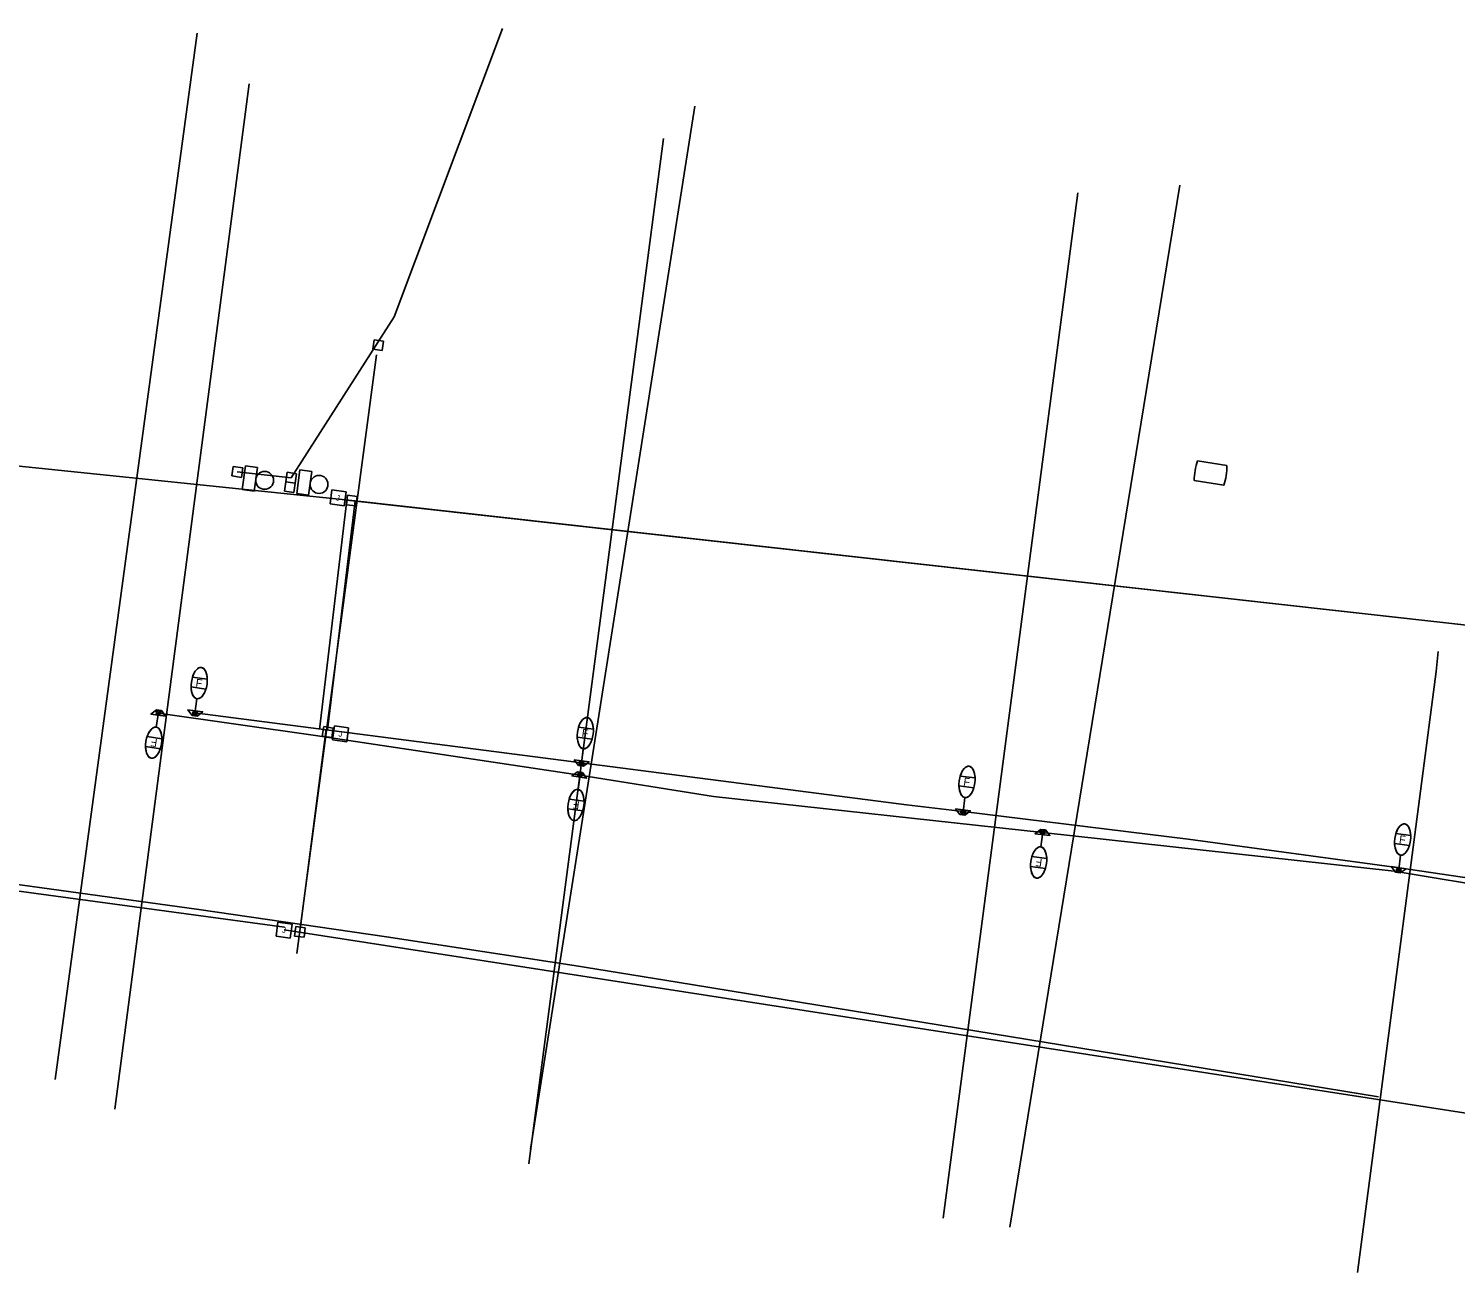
# Model space of a CAD drawing. Extents: x 915723 to 927758, y 636394 to 638609.
# Drawn here: x 924821 to 925539, y 636655 to 637280 of the extents above; entities that cross this region are included whole.
import ezdxf

# ---------------------------------------------------------------- set-up
doc = ezdxf.new("R2010")
doc.units = 0
for name, color, linetype in [('ConduitBM', 7, 'Continuous'), ('ConduitJB', 7, 'Continuous'), ('ConduitOT', 7, 'Continuous'), ('DrShaftConc', 7, 'Continuous'), ('LoadCenter', 7, 'Continuous'), ('Masonry_h', 7, 'Continuous'), ('Miscellaneous2', 7, 'Continuous'), ('PoleLight', 7, 'Continuous'), ('PullBox', 7, 'Continuous'), ('SchemHydraulicAux', 7, 'Continuous'), ('TextStructuresLabel', 7, 'Continuous')]:
    doc.layers.add(name, color=color, linetype=linetype)

msp = doc.modelspace()

# ---------------------------------------------------------------- linework, layer by layer
at = {"layer": 'ConduitBM'}
for p, q in [((924904.95, 636936.09), (925099.22, 636910.93)), ((924787.88, 636850.28), (924949.92, 636828.26)), ((925915.45, 636677.29), (924949.76, 636826.97))]:
    msp.add_line(p, q, dxfattribs=at)
for points in [[(924886.59, 636935.94), (924965.57, 636924.72), (925098.46, 636904.69)], [(925099.24, 636910.93), (925262.58, 636889.84), (925291.07, 636886.41)], [(925098.47, 636904.68), (925165.57, 636894.03), (925331.01, 636875.86)], [(925291.06, 636886.41), (925404.18, 636872.54), (925510.18, 636858.09)], [(925331.01, 636875.86), (925426.89, 636865.33), (925507.73, 636856.45), (925564.25, 636847.04)], [(925510.23, 636858.22), (925615.9, 636842.6), (925678.54, 636835.95), (925719.06, 636830.44)]]:
    msp.add_lwpolyline(points, dxfattribs=at)
at = {"layer": 'ConduitJB'}
for p, q in [((924783.08, 637063.49), (924983.84, 637042.69)), ((924983.84, 637042.69), (925933.76, 636936.47))]:
    msp.add_line(p, q, dxfattribs=at)
at = {"layer": 'ConduitOT'}
for p, q in [((924985.42, 637042.51), (924971.54, 636927.46)), ((924970.88, 636927.76), (924957.98, 636828.59))]:
    msp.add_line(p, q, dxfattribs=at)
at = {"layer": 'DrShaftConc'}
for p, q in [((924906.12, 637277.59), (924834.67, 636751.85)), ((925156.25, 637240.87), (925073.57, 636716.78)), ((925399.97, 637201.27), (925314.54, 636677.62)), ((924956.18, 636815.06), (924996.16, 637115.96)), ((924967.59, 636927.62), (924981.35, 637042.94)), ((925933.76, 636936.47), (924981.35, 637042.94))]:
    msp.add_line(p, q, dxfattribs=at)
msp.add_lwpolyline([(924148.09, 636918.61), (924243.21, 636911.23), (924338.26, 636903.05), (924433.24, 636894.08), (924528.14, 636884.3), (924622.95, 636873.74), (924717.68, 636862.37), (924812.3, 636850.22), (924906.82, 636837.27), (925001.23, 636823.53), (925095.52, 636808.99), (925147.31, 636800.67), (925147.31, 636800.67), (925499.92, 636743.14)], dxfattribs=at)
at = {"layer": 'LoadCenter'}
for p, q in [((924928.74, 637048.33), (924930.37, 637060.22)), ((924930.37, 637060.22), (924936.31, 637059.4)), ((924936.31, 637059.4), (924934.69, 637047.51)), ((924956.07, 637046.29), (924957.7, 637058.18)), ((924957.7, 637058.18), (924963.64, 637057.37)), ((924963.64, 637057.37), (924962.02, 637045.48)), ((924934.69, 637047.51), (924928.74, 637048.33)), ((924962.02, 637045.48), (924956.07, 637046.29))]:
    msp.add_line(p, q, dxfattribs=at)
for centre in [(924939.96, 637052.85), (924967.29, 637050.82)]:
    msp.add_circle(centre, 4.5, dxfattribs=at)
at = {"layer": 'Masonry_h'}
for p, q in [((924932.21, 637252.04), (924864.58, 636736.82)), ((925140.42, 637224.71), (925072.79, 636709.49)), ((925348.64, 637197.38), (925281.01, 636682.16)), ((925529.86, 636966.83), (925528.87, 636956.88)), ((925528.87, 636956.88), (925489.22, 636654.83))]:
    msp.add_line(p, q, dxfattribs=at)
at = {"layer": 'Miscellaneous2'}
for p, q in [((925423.67, 637060.25), (925408.84, 637062.67)), ((925408.84, 637062.67), (925408.84, 637062.67)), ((925407.23, 637052.8), (925407.23, 637052.8)), ((925407.23, 637052.8), (925422.06, 637050.38))]:
    msp.add_line(p, q, dxfattribs=at)
for start_param, end_param in [(1.249648, 1.891946), (4.391271, 5.033538), (4.391241, 4.391271)]:
    msp.add_ellipse((925415.45, 637056.52), major_axis=(2.55, 15.63), ratio=0.5, start_param=start_param, end_param=end_param, dxfattribs=at)
at = {"layer": 'PoleLight'}
for p, q in [((924903.71, 636953.98), (924911.15, 636952.91)), ((924910.44, 636947.96), (924903, 636949.03)), ((924904.9, 636935.78), (924905.95, 636943.13)), ((924886.65, 636936.21), (924885.48, 636928.88)), ((925097.74, 636928.78), (925105.19, 636927.82)), ((924880.92, 636924.12), (924888.34, 636922.93)), ((925104.55, 636922.86), (925097.1, 636923.82)), ((924887.55, 636917.99), (924880.13, 636919.18)), ((925099.18, 636910.6), (925100.13, 636917.96)), ((925098.48, 636904.96), (925097.5, 636897.6)), ((925296.41, 636898.36), (925288.96, 636899.34)), ((925289.61, 636904.29), (925297.06, 636903.32)), ((925093.05, 636892.73), (925100.5, 636891.73)), ((925291.02, 636886.11), (925291.98, 636893.47)), ((925099.83, 636886.77), (925092.39, 636887.77)), ((925331.06, 636876.04), (925330.07, 636868.68)), ((925508.58, 636875.33), (925516.03, 636874.35)), ((925325.63, 636863.81), (925333.07, 636862.81)), ((925515.38, 636869.39), (925507.93, 636870.37)), ((925509.98, 636857.15), (925510.95, 636864.51)), ((925332.41, 636857.86), (925324.96, 636858.86))]:
    msp.add_line(p, q, dxfattribs=at)
for points in [[(924888.05, 636937.26), (924885.57, 636937.59), (924882.76, 636935.45), (924890.19, 636934.44)], [(924888.05, 636937.26), (924885.57, 636937.59), (924882.76, 636935.45), (924890.19, 636934.44)], [(924906.03, 636934.44), (924903.56, 636934.76), (924901.4, 636937.56), (924908.83, 636936.59)], [(924906.03, 636934.44), (924903.56, 636934.76), (924901.4, 636937.56), (924908.83, 636936.59)], [(925100.23, 636909.28), (925097.75, 636909.61), (925095.59, 636912.41), (925103.03, 636911.44)], [(925100.23, 636909.28), (925097.75, 636909.61), (925095.59, 636912.41), (925103.03, 636911.44)], [(925099.72, 636906.01), (925097.25, 636906.39), (925094.4, 636904.3), (925101.81, 636903.16)], [(925099.72, 636906.01), (925097.25, 636906.39), (925094.4, 636904.3), (925101.81, 636903.16)], [(925291.93, 636884.64), (925289.45, 636884.95), (925287.28, 636887.74), (925294.72, 636886.81)], [(925291.93, 636884.64), (925289.45, 636884.95), (925287.28, 636887.74), (925294.72, 636886.81)], [(925332.47, 636877.21), (925329.98, 636877.47), (925327.23, 636875.27), (925334.68, 636874.45)], [(925332.47, 636877.21), (925329.98, 636877.47), (925327.23, 636875.27), (925334.68, 636874.45)], [(925510.81, 636855.63), (925508.35, 636856.02), (925506.26, 636858.87), (925513.67, 636857.72)], [(925510.81, 636855.63), (925508.35, 636856.02), (925506.26, 636858.87), (925513.67, 636857.72)]]:
    msp.add_lwpolyline(points, close=True, dxfattribs=at)
for centre, radius in [((924886.65, 636936.19), 1.14), ((924886.65, 636936.21), 0.569), ((924904.94, 636935.84), 1.14), ((924904.9, 636935.78), 0.569), ((925099.21, 636910.72), 1.14), ((925099.18, 636910.6), 0.569), ((925098.48, 636904.89), 1.14), ((925098.48, 636904.96), 0.569), ((925291.02, 636886.11), 1.14), ((925291.02, 636886.11), 0.569), ((925331.06, 636876.04), 1.14), ((925331.06, 636876.04), 0.569), ((925509.98, 636857.15), 1.14), ((925509.98, 636857.15), 0.569)]:
    msp.add_circle(centre, radius, dxfattribs=at)
for centre, major_axis in [((924907.07, 636950.97), (-1.12, -7.84)), ((924884.23, 636921.06), (1.25, 7.82)), ((925101.14, 636925.82), (-1.01, -7.85)), ((925293.01, 636901.33), (-1.03, -7.85)), ((925096.44, 636889.75), (1.05, 7.85)), ((925511.98, 636872.36), (-1.03, -7.85)), ((925329.02, 636860.84), (1.05, 7.85))]:
    msp.add_ellipse(centre, major_axis=major_axis, ratio=0.5, dxfattribs=at)
for centre, major_axis, start_param, end_param in [((924907.07, 636950.97), (-1.12, -7.84), 1.891945, 4.391241), ((924907.07, 636950.97), (-1.12, -7.84), 5.033538, 6.283185), ((924907.07, 636950.97), (-1.12, -7.84), 0, 0.847605), ((924907.07, 636950.97), (-1.12, -7.84), 0.847605, 1.249648), ((924884.23, 636921.06), (1.25, 7.82), 0, 0.847605), ((924884.23, 636921.06), (1.25, 7.82), 5.033538, 6.283185), ((925101.14, 636925.82), (-1.01, -7.85), 1.891945, 4.391241), ((924884.23, 636921.06), (1.25, 7.82), 0.847605, 1.249648), ((925101.14, 636925.82), (-1.01, -7.85), 5.033538, 6.283185), ((925101.14, 636925.82), (-1.01, -7.85), 0.847605, 1.249648), ((924884.23, 636921.06), (1.25, 7.82), 1.891945, 4.391241), ((925101.14, 636925.82), (-1.01, -7.85), 0, 0.847605), ((925293.01, 636901.33), (-1.03, -7.85), 1.891945, 4.391241), ((925293.01, 636901.33), (-1.03, -7.85), 5.033538, 6.283185), ((925096.44, 636889.75), (1.05, 7.85), 0.847605, 1.249648), ((925096.44, 636889.75), (1.05, 7.85), 0, 0.847605), ((925096.44, 636889.75), (1.05, 7.85), 5.033538, 6.283185), ((925293.01, 636901.33), (-1.03, -7.85), 0, 0.847605), ((925293.01, 636901.33), (-1.03, -7.85), 0.847605, 1.249648), ((925096.44, 636889.75), (1.05, 7.85), 1.891945, 4.391241), ((925511.98, 636872.36), (-1.03, -7.85), 1.891945, 4.391241), ((925329.02, 636860.84), (1.05, 7.85), 0.847605, 1.249648), ((925329.02, 636860.84), (1.05, 7.85), 0, 0.847605), ((925329.02, 636860.84), (1.05, 7.85), 5.033538, 6.283185), ((925511.98, 636872.36), (-1.03, -7.85), 5.033538, 6.283185), ((925511.98, 636872.36), (-1.03, -7.85), 0, 0.847605), ((925511.98, 636872.36), (-1.03, -7.85), 0.847605, 1.249648), ((925329.02, 636860.84), (1.05, 7.85), 1.891945, 4.391241)]:
    msp.add_ellipse(centre, major_axis=major_axis, ratio=0.5, start_param=start_param, end_param=end_param, dxfattribs=at)
at = {"layer": 'PullBox'}
for p, q in [((924994.27, 637118.75), (924994.98, 637123.51)), ((924994.98, 637123.51), (924999.73, 637122.79)), ((924999.73, 637122.79), (924999.02, 637118.04)), ((924999.02, 637118.04), (924994.27, 637118.75)), ((924923.5, 637055.05), (924924.21, 637059.8)), ((924924.21, 637059.8), (924928.96, 637059.09)), ((924928.96, 637059.09), (924928.25, 637054.33)), ((924928.25, 637054.33), (924923.5, 637055.05)), ((924949.87, 637047.41), (924950.58, 637052.16)), ((924950.58, 637052.16), (924951.29, 637056.91)), ((924955.33, 637051.45), (924950.58, 637052.16)), ((924950.58, 637052.16), (924955.33, 637051.45)), ((924951.29, 637056.91), (924956.04, 637056.2)), ((924955.33, 637051.45), (924954.62, 637046.7)), ((924956.04, 637056.2), (924955.33, 637051.45)), ((924954.62, 637046.7), (924949.87, 637047.41)), ((924972.89, 637041), (924973.81, 637048.06)), ((924973.81, 637048.06), (924980.87, 637047.14)), ((924980.87, 637047.14), (924979.95, 637040.08)), ((924981.08, 637040.58), (924981.62, 637045.35)), ((924981.62, 637045.35), (924986.39, 637044.81)), ((924986.39, 637044.81), (924985.85, 637040.04)), ((924979.95, 637040.08), (924972.89, 637041)), ((924985.85, 637040.04), (924981.08, 637040.58)), ((924968.94, 636924.35), (924969.64, 636929.11)), ((924969.64, 636929.11), (924974.39, 636928.41)), ((924974.39, 636928.41), (924973.7, 636923.66)), ((924974.13, 636922.39), (924975.05, 636929.46)), ((924975.05, 636929.46), (924982.12, 636928.54)), ((924982.12, 636928.54), (924981.2, 636921.47)), ((924973.7, 636923.66), (924968.94, 636924.35)), ((924981.2, 636921.47), (924974.13, 636922.39)), ((924945.75, 636823.78), (924946.67, 636830.84)), ((924946.67, 636830.84), (924953.73, 636829.92)), ((924953.73, 636829.92), (924952.81, 636822.86)), ((924955.02, 636823.83), (924955.56, 636828.61)), ((924955.56, 636828.61), (924960.33, 636828.07)), ((924960.33, 636828.07), (924959.8, 636823.3)), ((924952.81, 636822.86), (924945.75, 636823.78)), ((924959.8, 636823.3), (924955.02, 636823.83))]:
    msp.add_line(p, q, dxfattribs=at)
at = {"layer": 'SchemHydraulicAux'}
for p, q in [((925004.99, 637134.95), (925059.59, 637279.9)), ((924953.31, 637054.18), (925004.99, 637134.95)), ((924926.23, 637057.07), (924953.31, 637054.18))]:
    msp.add_line(p, q, dxfattribs=at)

# ---------------------------------------------------------------- texts
at = {"layer": 'ConduitOT'}
for p in [(924975.74, 637042.78), (924976.98, 636924.18), (924948.6, 636825.56)]:
    msp.add_text('J', height=2.85, rotation=352.57842, dxfattribs=at).set_placement(p)
at = {"layer": 'TextStructuresLabel'}
for rotation, p in [(351.84774, (924905.07, 636949.24)), (352.63988, (925099.16, 636924.06)), (170.91347, (924886.26, 636922.76)), (352.54725, (925291.02, 636899.57)), (172.36052, (925098.43, 636891.5)), (352.50287, (925509.99, 636870.61)), (172.36442, (925331.01, 636862.59))]:
    msp.add_text('F', height=4, rotation=rotation, dxfattribs=at).set_placement(p)

doc.saveas('drawing.dxf')
